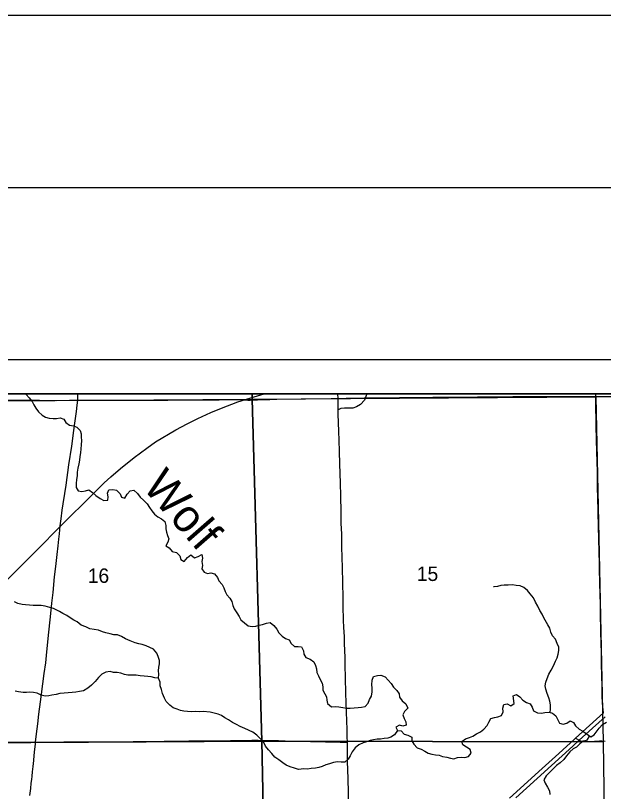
# Model space of a CAD drawing. Extents: x 0 to 34, y 0 to 22.
# Drawn here: x 5.364 to 7.072, y 19.744 to 22 of the extents above; entities that cross this region are included whole.
import ezdxf

# ---------------------------------------------------------------- set-up
doc = ezdxf.new("R2010")
doc.units = 0
for name, color, linetype in [('Default', 7, 'Continuous'), ('GM_X_County_Road', 7, 'Continuous'), ('GM_X_Interstate_Route', 7, 'Continuous'), ('GM_X_Minor_River', 7, 'Continuous'), ('GM_X_Minor_River_Text', 7, 'Continuous'), ('GM_X_Rail_Line', 7, 'Continuous'), ('GM_X_Section', 7, 'Continuous'), ('GM_X_Section_Text', 7, 'Continuous'), ('GM_X_Township_Road', 7, 'Continuous'), ('GM_X_US_Route', 7, 'Continuous'), ('SH_Border', 7, 'Continuous'), ('SH_Cut_Line', 7, 'Continuous'), ('SH_Data', 7, 'Continuous')]:
    doc.layers.add(name, color=color, linetype=linetype)

msp = doc.modelspace()

# ---------------------------------------------------------------- linework, layer by layer
at = {"layer": 'Default'}
for points in [[(6.0512, 20.9), (5.0488, 20.9), (5.0494, 20.8782), (6.0515, 20.8843)], [(7.0497, 20.9), (6.0512, 20.9), (6.0515, 20.8843), (7.0499, 20.8916)]]:
    msp.add_lwpolyline(points, close=True, dxfattribs=at)
at = {"layer": 'GM_X_County_Road'}
msp.add_line((6.3011, 20.8868), (6.3009, 20.9), dxfattribs=at)
for points in [[(6.3011, 20.8868), (6.3247, 20.8872), (6.3775, 20.8881), (6.3962, 20.8882), (6.4117, 20.8885), (6.4396, 20.8889), (6.48, 20.8894), (6.5359, 20.89), (6.5763, 20.8906), (6.6073, 20.8905), (6.657, 20.8908), (6.7067, 20.8912), (6.7782, 20.8919), (6.8092, 20.8921), (6.8589, 20.8923), (6.9086, 20.8923), (6.9583, 20.8922), (7.0112, 20.8923), (7.0499, 20.8923)], [(7.0499, 20.8923), (7.0577, 20.8923), (7.0888, 20.8923), (7.1447, 20.8923), (7.182, 20.8924), (7.2473, 20.8928), (7.3063, 20.8935), (7.3684, 20.8939), (7.3995, 20.894), (7.4492, 20.8947), (7.5237, 20.8952), (7.5517, 20.8954), (7.5734, 20.8957), (7.62, 20.8958), (7.6604, 20.8959), (7.7132, 20.8958), (7.7443, 20.8958), (7.825, 20.8954), (7.884, 20.8951), (7.9337, 20.895), (7.9959, 20.8949), (8.0672, 20.8949)], [(5.3403, 20.8821), (5.3838, 20.8819), (5.4335, 20.8814), (5.4832, 20.8812), (5.5205, 20.8814), (5.545, 20.8814)], [(5.545, 20.8814), (5.5671, 20.8815), (5.6478, 20.8818), (5.6789, 20.8819), (5.7317, 20.882), (5.8062, 20.8822), (5.9026, 20.8824), (5.9554, 20.8825), (6.0071, 20.8838), (6.018, 20.8838), (6.0285, 20.8831), (6.0387, 20.882), (6.0462, 20.882), (6.0668, 20.8828), (6.1028, 20.8841), (6.123, 20.8846), (6.2068, 20.8857), (6.2816, 20.8869), (6.3011, 20.8868)], [(6.3288, 19.8879), (6.3281, 19.9026), (6.3273, 19.9255), (6.3263, 19.9489), (6.3259, 19.9754), (6.3251, 20.0016), (6.3242, 20.0309), (6.3231, 20.0731), (6.322, 20.1124), (6.3214, 20.1325), (6.3208, 20.1545), (6.3199, 20.1732), (6.3194, 20.1937), (6.3183, 20.2219), (6.3173, 20.2408), (6.3162, 20.284), (6.3157, 20.3117), (6.3147, 20.3467), (6.3137, 20.3994), (6.3132, 20.4202), (6.3126, 20.4595), (6.3118, 20.4919), (6.3106, 20.5238), (6.3098, 20.5563), (6.309, 20.6035), (6.3078, 20.6408), (6.307, 20.6684), (6.3062, 20.697), (6.3049, 20.7329), (6.304, 20.7651), (6.3033, 20.7905), (6.3017, 20.8419), (6.3015, 20.8597), (6.301, 20.88), (6.3011, 20.8868)], [(4.5719, 19.8854), (4.5835, 19.8853), (4.63, 19.886), (4.6797, 19.8866), (4.7944, 19.886), (4.8503, 19.8854), (4.8937, 19.8856), (4.9272, 19.8858), (4.9706, 19.886), (4.9955, 19.8863), (5.0141, 19.8864), (5.0482, 19.8864), (5.0698, 19.8867), (5.1008, 19.8866), (5.135, 19.8867), (5.166, 19.8869), (5.1847, 19.8868), (5.2747, 19.8873), (5.3057, 19.8876), (5.3243, 19.8876), (5.3491, 19.8875), (5.3771, 19.8876), (5.3988, 19.8875), (5.4225, 19.8877)], [(5.4225, 19.8877), (5.4329, 19.8877), (5.4515, 19.8878), (5.4795, 19.8879), (5.5043, 19.888), (5.5477, 19.8881), (5.5695, 19.8882), (5.5943, 19.8882), (5.6191, 19.8884), (5.6688, 19.8889), (5.7061, 19.8893), (5.7651, 19.8897), (5.7961, 19.89), (5.8333, 19.8905), (5.8675, 19.8912), (5.9016, 19.8913), (5.9295, 19.8915), (5.9667, 19.8918), (5.9884, 19.8921), (6.0256, 19.8927), (6.0505, 19.893), (6.0691, 19.8931), (6.0969, 19.8926), (6.1279, 19.892), (6.1683, 19.8909), (6.1962, 19.8904), (6.221, 19.8899), (6.2365, 19.8894), (6.2643, 19.8886), (6.2892, 19.888), (6.3077, 19.8877), (6.3201, 19.8878), (6.3288, 19.8879)], [(6.3403, 19.2924), (6.3401, 19.2991), (6.3397, 19.3075), (6.339, 19.3239), (6.3378, 19.3605), (6.3372, 19.3796), (6.3366, 19.4139), (6.3365, 19.4358), (6.3365, 19.4792), (6.3359, 19.5239), (6.334, 19.5995), (6.3332, 19.6622), (6.3324, 19.6969), (6.3318, 19.7398), (6.3303, 19.7815), (6.3297, 19.8065), (6.329, 19.8322), (6.3289, 19.8539), (6.329, 19.8744), (6.3288, 19.8879)]]:
    msp.add_lwpolyline(points, dxfattribs=at)
at = {"layer": 'GM_X_Interstate_Route'}
msp.add_lwpolyline([(8.1285, 16.8707), (8.1148, 17.8694), (8.0976, 18.2853), (8.0958, 18.3144), (8.0817, 18.88), (8.0959, 19.2713), (8.1023, 19.3817), (8.0929, 19.6339), (8.0678, 20.8562), (8.0675, 20.8733), (8.067, 20.8954), (8.0669, 20.9), (3.0331, 20.9), (3.0588, 19.9042), (3.067, 19.3838), (3.0747, 18.8969), (3.0724, 18.2926), (3.0939, 16.8719)], dxfattribs=at)
at = {"layer": 'GM_X_Minor_River'}
for points in [[(5.3944, 20.9), (5.3951, 20.8986), (5.4037, 20.8883), (5.412, 20.8776), (5.4176, 20.8681), (5.4228, 20.8582), (5.4307, 20.8482), (5.4412, 20.8382), (5.451, 20.8328), (5.4615, 20.8297), (5.4729, 20.8281), (5.4835, 20.8287), (5.4934, 20.8301), (5.5039, 20.8263), (5.5103, 20.8167), (5.5208, 20.8094), (5.5322, 20.807), (5.542, 20.8035), (5.5514, 20.7939), (5.5547, 20.784), (5.555, 20.7745), (5.5557, 20.7647), (5.5544, 20.7518), (5.5539, 20.7404), (5.5531, 20.7283), (5.5507, 20.7184), (5.5502, 20.707), (5.5483, 20.6964), (5.5455, 20.6836), (5.5431, 20.6726), (5.5431, 20.6631), (5.5411, 20.6506), (5.5402, 20.64), (5.5405, 20.6282), (5.5457, 20.6179), (5.5563, 20.6159), (5.5673, 20.6181), (5.5772, 20.621), (5.5873, 20.613), (5.5975, 20.6045), (5.6095, 20.596), (5.6204, 20.5902), (5.6318, 20.5913), (5.633, 20.6011), (5.6316, 20.611), (5.6351, 20.6208), (5.6472, 20.6219), (5.6578, 20.6199), (5.6676, 20.6099), (5.6716, 20.6), (5.6818, 20.5972), (5.688, 20.6086), (5.6972, 20.6183), (5.7074, 20.6198), (5.7183, 20.6109), (5.7258, 20.5995), (5.7359, 20.591), (5.7468, 20.5807), (5.7536, 20.57), (5.7599, 20.5604), (5.7682, 20.5501), (5.7779, 20.5428), (5.7881, 20.537), (5.7979, 20.5289), (5.8005, 20.5175), (5.8007, 20.5077), (5.8026, 20.4982), (5.8055, 20.4883), (5.8092, 20.4787), (5.8065, 20.4689), (5.8003, 20.4583), (5.8101, 20.4522), (5.8195, 20.4418), (5.832, 20.4387), (5.8414, 20.4291), (5.8443, 20.4188), (5.8541, 20.413), (5.8637, 20.4247), (5.8736, 20.4322), (5.8841, 20.4238), (5.8951, 20.4271), (5.905, 20.433), (5.9072, 20.4228), (5.9056, 20.4129)], [(6.3843, 20.9), (6.3815, 20.8925), (6.3776, 20.8815), (6.3662, 20.8691), (6.3544, 20.862), (6.3437, 20.8583), (6.3195, 20.8585), (6.3096, 20.8571), (6.2998, 20.853), (6.3013, 20.8526)], [(5.9056, 20.4129), (5.9074, 20.4015), (5.905, 20.3913), (5.9121, 20.3818), (5.922, 20.3779), (5.9318, 20.3797), (5.942, 20.3769), (5.951, 20.3666), (5.9551, 20.3563), (5.9641, 20.346), (5.9697, 20.336), (5.973, 20.3258), (5.9775, 20.3162), (5.9869, 20.3063), (5.9924, 20.2964), (5.9958, 20.2853), (5.9995, 20.2747), (6.0066, 20.2632), (6.0137, 20.2525), (6.0185, 20.243), (6.0294, 20.2349), (6.0403, 20.2253), (6.0513, 20.2241), (6.0623, 20.2251), (6.0718, 20.2277), (6.0812, 20.2295), (6.093, 20.2332), (6.1036, 20.2353), (6.1149, 20.2265), (6.1235, 20.2158), (6.1295, 20.2055), (6.1385, 20.1959), (6.1487, 20.1886), (6.1589, 20.1851), (6.1652, 20.174), (6.175, 20.1656), (6.1848, 20.1655), (6.1947, 20.1646), (6.201, 20.1528), (6.2021, 20.1429), (6.208, 20.1334), (6.2197, 20.1287), (6.231, 20.1214), (6.2355, 20.1107), (6.2381, 20.1005), (6.2391, 20.0902), (6.2447, 20.0799), (6.2488, 20.0696), (6.2547, 20.0589), (6.2565, 20.0483), (6.2565, 20.0384), (6.2632, 20.0285), (6.268, 20.019), (6.2687, 20.0095), (6.2709, 20), (6.2818, 19.99), (6.2924, 19.991), (6.3034, 19.9906), (6.3147, 19.9882), (6.3257, 19.9865), (6.3367, 19.9861), (6.3484, 19.9871), (6.3598, 19.9881), (6.3693, 19.9891), (6.3795, 19.9909), (6.389, 20.0007), (6.3929, 20.0117), (6.3979, 20.0215), (6.4003, 20.0336), (6.4, 20.045), (6.399, 20.0545), (6.3998, 20.0674), (6.4045, 20.0783), (6.4159, 20.0817), (6.4257, 20.0827), (6.4378, 20.0773), (6.4468, 20.0673), (6.455, 20.0577), (6.4618, 20.0474), (6.4723, 20.0378), (6.4783, 20.0283), (6.4801, 20.0184), (6.4876, 20.0081), (6.4981, 19.9993), (6.504, 19.9863), (6.4941, 19.9769), (6.4895, 19.9671), (6.4932, 19.9568), (6.4984, 19.9462), (6.4995, 19.9367), (6.4892, 19.9341), (6.4794, 19.9369), (6.4691, 19.9313), (6.4739, 19.921), (6.4849, 19.9209), (6.4936, 19.9105), (6.5041, 19.9078), (6.5151, 19.9024), (6.5153, 19.8914), (6.5213, 19.8814), (6.5307, 19.8715)], [(6.9176, 19.9736), (6.9183, 19.9834), (6.9184, 19.9959), (6.9166, 20.0066), (6.9136, 20.0165), (6.9092, 20.0287), (6.9048, 20.0416), (6.9033, 20.0511), (6.9053, 20.0621), (6.9084, 20.073), (6.9138, 20.0848), (6.9204, 20.0972), (6.9273, 20.1097), (6.9331, 20.1229), (6.9381, 20.1331), (6.9412, 20.1437), (6.9428, 20.1539), (6.9425, 20.1638), (6.9381, 20.1744), (6.9325, 20.187), (6.9247, 20.197), (6.9198, 20.2069), (6.9161, 20.2187), (6.9109, 20.2286), (6.899, 20.2488), (6.8941, 20.2599), (6.887, 20.2706), (6.8818, 20.2827), (6.8744, 20.295), (6.8688, 20.3072), (6.859, 20.3183), (6.8516, 20.3282), (6.8414, 20.3374), (6.8305, 20.3417), (6.8184, 20.3433), (6.8085, 20.3445), (6.7953, 20.3439), (6.7835, 20.344), (6.7737, 20.3434), (6.7642, 20.34), (6.7543, 20.339), (6.7532, 20.339)], [(5.4746, 20.276), (5.4637, 20.2791), (5.4505, 20.283), (5.4383, 20.2847), (5.4156, 20.2849), (5.405, 20.2858), (5.3929, 20.287), (5.3831, 20.2879), (5.371, 20.2903), (5.3612, 20.2957)], [(6.4739, 19.921), (6.4648, 19.9085), (6.4548, 19.9018), (6.4454, 19.8989), (6.4348, 19.8986), (6.4245, 19.8964), (6.4147, 19.8965), (6.404, 19.8947), (6.3942, 19.8922), (6.3839, 19.8888), (6.3737, 19.8852), (6.3619, 19.8796), (6.3512, 19.8713), (6.342, 19.8597), (6.3366, 19.848), (6.3309, 19.8381), (6.3213, 19.8291), (6.31, 19.8292), (6.2997, 19.8305), (6.288, 19.8283), (6.2762, 19.8246), (6.2656, 19.8213), (6.2549, 19.8169), (6.2451, 19.8136), (6.2352, 19.8121), (6.2235, 19.8107), (6.2121, 19.809), (6.2019, 19.8098), (6.1867, 19.8081), (6.1746, 19.8116), (6.1618, 19.8155), (6.1505, 19.8209), (6.1407, 19.8271), (6.129, 19.8359), (6.1177, 19.8436), (6.1087, 19.8547), (6.0986, 19.8651), (6.0903, 19.8754), (6.0851, 19.8861), (6.075, 19.8979), (6.0652, 19.9079), (6.0536, 19.9167), (6.0302, 19.9268), (6.0166, 19.9326), (6.0061, 19.9384), (5.9948, 19.9446), (5.9831, 19.9527), (5.9725, 19.9585), (5.9627, 19.9647), (5.9529, 19.9689), (5.9408, 19.9721), (5.9299, 19.9752), (5.9094, 19.9762), (5.8992, 19.9759), (5.886, 19.9764), (5.8754, 19.9761), (5.8636, 19.9766), (5.8534, 19.9775), (5.8432, 19.9799), (5.8334, 19.983), (5.8217, 19.9873), (5.8119, 19.995), (5.8021, 20.0053), (5.7973, 20.0152), (5.7914, 20.0289), (5.7884, 20.0411), (5.7844, 20.051), (5.7841, 20.0624), (5.7793, 20.0738), (5.7801, 20.0848), (5.7798, 20.0947), (5.7807, 20.1053), (5.7819, 20.1155), (5.7827, 20.1254), (5.7787, 20.1368), (5.7746, 20.1463), (5.7652, 20.1582), (5.7539, 20.1628), (5.7437, 20.1675), (5.732, 20.171), (5.7222, 20.173), (5.7116, 20.1765), (5.6972, 20.182), (5.684, 20.1878), (5.6724, 20.1944), (5.6603, 20.1994), (5.6501, 20.1995), (5.6387, 20.2023), (5.6266, 20.2051), (5.6164, 20.2078), (5.6055, 20.2132), (5.5798, 20.2173), (5.5681, 20.2231), (5.5549, 20.2278), (5.5432, 20.237), (5.5334, 20.2424), (5.5232, 20.2489), (5.5135, 20.2559), (5.5018, 20.2613), (5.492, 20.2671), (5.4746, 20.276)], [(5.7793, 20.0738), (5.7687, 20.0747), (5.7585, 20.0774), (5.7486, 20.0787), (5.738, 20.0795), (5.7259, 20.0808), (5.7142, 20.0824), (5.7013, 20.0822), (5.6907, 20.0827), (5.6809, 20.0846), (5.6703, 20.0882), (5.659, 20.0902), (5.6487, 20.0903), (5.6389, 20.093), (5.6264, 20.0912), (5.6146, 20.0849), (5.6051, 20.0755), (5.5951, 20.0639), (5.5848, 20.0529), (5.5738, 20.0443), (5.5616, 20.0372), (5.5498, 20.0347), (5.5392, 20.0329), (5.5282, 20.0315), (5.5172, 20.0312), (5.5055, 20.0298), (5.4926, 20.0292), (5.482, 20.0263), (5.4698, 20.0241), (5.4603, 20.0223), (5.4497, 20.0209), (5.4388, 20.0244), (5.4267, 20.0302), (5.4161, 20.0322), (5.4059, 20.0331), (5.3957, 20.0316), (5.3858, 20.0321), (5.373, 20.0338), (5.3628, 20.0358)], [(6.5307, 19.8715), (6.5424, 19.8676), (6.553, 19.861), (6.5628, 19.8552), (6.5737, 19.8525), (6.5839, 19.8509), (6.5945, 19.85), (6.6051, 19.8461), (6.6168, 19.8437), (6.6278, 19.8409), (6.6376, 19.8393), (6.6478, 19.8426), (6.66, 19.8437), (6.6698, 19.8432), (6.6804, 19.8457), (6.6877, 19.8559), (6.6852, 19.8666), (6.6742, 19.8727), (6.6637, 19.88), (6.6607, 19.8899), (6.6714, 19.897), (6.6828, 19.9011), (6.6927, 19.9052), (6.7037, 19.9115), (6.7147, 19.9171), (6.7247, 19.9257), (6.7346, 19.9355), (6.7392, 19.9453), (6.7454, 19.9559), (6.7556, 19.9592), (6.7655, 19.961), (6.7757, 19.9647), (6.7808, 19.9753), (6.7801, 19.9859), (6.7825, 19.9969), (6.7927, 19.9987), (6.8032, 19.9929), (6.8132, 20.0004), (6.8096, 20.0224), (6.8194, 20.0261), (6.8292, 20.0196), (6.8379, 20.01), (6.8484, 20.0031), (6.8593, 19.9988), (6.8649, 19.9892), (6.869, 19.9782), (6.8811, 19.9728), (6.8921, 19.9715), (6.9019, 19.9741), (6.9144, 19.9743), (6.9246, 19.972), (6.9344, 19.9643), (6.9396, 19.9525), (6.9448, 19.9429), (6.955, 19.9402), (6.9656, 19.9427), (6.9752, 19.9498), (6.9854, 19.9444), (6.9913, 19.9349), (7.0015, 19.9257), (7.0128, 19.9199), (7.0354, 19.903), (7.0453, 19.9089), (7.0598, 19.9285), (7.0697, 19.9387), (7.0808, 19.9454)], [(7.0315, 19.9059), (7.0228, 19.8925), (7.0129, 19.8903), (7.0034, 19.8824), (6.9942, 19.8726), (6.9847, 19.8686), (6.9744, 19.8592), (6.9652, 19.8475), (6.9575, 19.837), (6.9469, 19.8276), (6.9354, 19.8193), (6.9247, 19.8084), (6.9152, 19.7994), (6.9056, 19.7897), (6.8995, 19.7783), (6.9032, 19.7681), (6.9095, 19.757), (6.9151, 19.7459), (6.9169, 19.7357)]]:
    msp.add_lwpolyline(points, dxfattribs=at)
at = {"layer": 'GM_X_Rail_Line'}
msp.add_lwpolyline([(5.1293, 20.1489), (5.3848, 20.4049), (5.4269, 20.4471), (5.494, 20.5144), (5.5916, 20.6116), (5.6217, 20.6412), (5.6411, 20.6592), (5.6687, 20.6829), (5.7087, 20.7153), (5.7453, 20.7422), (5.7709, 20.7604), (5.8302, 20.7959), (5.8631, 20.8132), (5.8936, 20.8285), (5.9313, 20.8456), (5.9622, 20.8588), (6.0095, 20.8766), (6.0574, 20.8917), (6.0867, 20.9)], dxfattribs=at)
at = {"layer": 'GM_X_Section'}
for points in [[(7.0499, 20.8916), (7.0719, 19.8884), (6.0796, 19.8902), (6.0515, 20.8843)], [(6.0515, 20.8843), (6.0796, 19.8902), (5.0715, 19.8844), (5.0494, 20.8782)], [(6.0796, 19.8902), (6.0998, 18.8817), (5.0689, 18.882), (5.0715, 19.8844)], [(7.0719, 19.8884), (7.0785, 19.4112), (7.105, 18.883), (6.0998, 18.8817), (6.0796, 19.8902)]]:
    msp.add_lwpolyline(points, close=True, dxfattribs=at)
at = {"layer": 'GM_X_Township_Road'}
for p, q in [((7.0499, 20.8923), (7.0497, 20.9)), ((6.9914, 19.8991), (7.0015, 19.8931))]:
    msp.add_line(p, q, dxfattribs=at)
for points in [[(5.545, 20.8814), (5.5452, 20.8833), (5.5451, 20.9)], [(7.0728, 19.9727), (7.0716, 19.9815), (7.0708, 19.9901), (7.0698, 20.0028), (7.069, 20.0215), (7.0683, 20.0495), (7.067, 20.1147), (7.0663, 20.1457), (7.0654, 20.1767), (7.0646, 20.2077), (7.0644, 20.2201), (7.064, 20.2543), (7.0633, 20.2853), (7.0626, 20.3195), (7.0619, 20.3474), (7.0612, 20.394), (7.0609, 20.4127), (7.0602, 20.4343), (7.0589, 20.484), (7.0584, 20.5089), (7.0568, 20.5617), (7.0553, 20.6299), (7.0549, 20.6731), (7.0531, 20.7322), (7.0523, 20.7665), (7.0515, 20.807), (7.0509, 20.8318), (7.0504, 20.8536), (7.0502, 20.8722), (7.05, 20.8908), (7.0499, 20.8923)], [(5.4225, 19.8877), (5.425, 19.9122), (5.4285, 19.9406), (5.4321, 19.9691), (5.4369, 20.0045), (5.4394, 20.0268), (5.4433, 20.0568), (5.447, 20.087), (5.4517, 20.1185), (5.4536, 20.139), (5.46, 20.1986), (5.4655, 20.2521), (5.4696, 20.2916), (5.473, 20.3229), (5.4776, 20.3678), (5.4811, 20.3979), (5.4852, 20.4332), (5.4879, 20.4579), (5.4901, 20.4773), (5.4915, 20.4928), (5.4937, 20.5162), (5.4963, 20.5366), (5.4999, 20.562), (5.5026, 20.5804), (5.5073, 20.6106), (5.5107, 20.6345), (5.5193, 20.6934), (5.5272, 20.7479), (5.5337, 20.7939), (5.5373, 20.8215), (5.541, 20.849), (5.5432, 20.8674), (5.545, 20.8814)], [(5.4055, 19.7324), (5.408, 19.7531), (5.4097, 19.7686), (5.4109, 19.7787), (5.412, 19.789), (5.4134, 19.8013), (5.415, 19.8164), (5.4169, 19.8344), (5.4185, 19.8492), (5.4205, 19.8673), (5.4218, 19.8816), (5.4225, 19.8877)], [(7.0015, 19.8931), (7.0058, 19.8912), (7.0104, 19.89), (7.0145, 19.8893), (7.0203, 19.8891), (7.0313, 19.8897), (7.061, 19.891), (7.068, 19.8912), (7.0774, 19.8907)]]:
    msp.add_lwpolyline(points, dxfattribs=at)
at = {"layer": 'GM_X_US_Route'}
for points in [[(6.7998, 19.725), (6.8411, 19.7628), (6.8849, 19.8024), (6.9425, 19.8546), (6.9884, 19.8965), (6.9914, 19.8991), (7.0322, 19.9361), (7.0728, 19.9727)], [(6.8174, 19.7258), (6.983, 19.8762), (7.0015, 19.8931), (7.0407, 19.9284), (7.0771, 19.9614)]]:
    msp.add_lwpolyline(points, dxfattribs=at)
at = {"layer": 'SH_Border'}
msp.add_lwpolyline([(1.5, 21.5), (33.5, 21.5), (33.5, 0.5), (1.5, 0.5)], close=True, dxfattribs=at)
at = {"layer": 'SH_Cut_Line'}
msp.add_lwpolyline([(0, 0), (34, 0), (34, 22), (0, 22)], close=True, dxfattribs=at)
msp.add_lwpolyline([(8.1285, 16.8707), (8.1148, 17.8694), (8.0976, 18.2853), (8.0958, 18.3144), (8.0817, 18.88), (8.0959, 19.2713), (8.1023, 19.3817), (8.0929, 19.6339), (8.0678, 20.8562), (8.0675, 20.8733), (8.067, 20.8954), (8.0669, 20.9), (2.1, 20.9), (2.1, 14.1)], dxfattribs=at)
at = {"layer": 'SH_Data'}
for p, q in [((2, 21), (9, 21)), ((2.1, 20.9), (8.9, 20.9))]:
    msp.add_line(p, q, dxfattribs=at)

# ---------------------------------------------------------------- texts
at = {"layer": 'GM_X_Minor_River_Text'}
msp.add_text('Wolf', height=0.09473, rotation=311.1684, dxfattribs=at).set_placement((5.7304, 20.6282))
at = {"layer": 'GM_X_Section_Text'}
for s, p in [('16', (5.5738, 20.3506)), ('15', (6.53, 20.3561))]:
    msp.add_text(s, height=0.04186, rotation=0, dxfattribs=at).set_placement(p)

doc.saveas('drawing.dxf')
